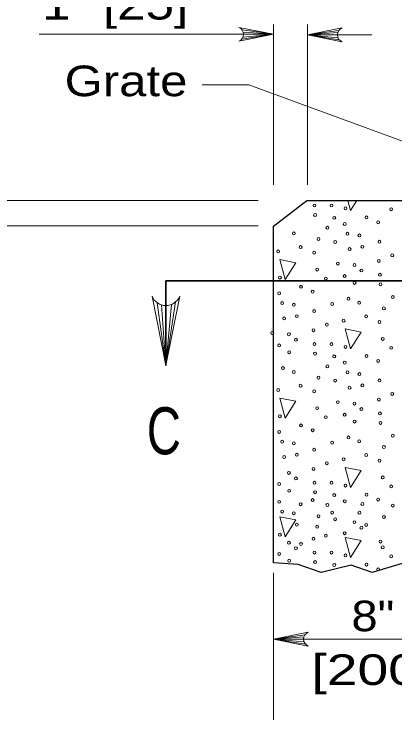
# Model space of a CAD drawing. Extents: x -410.5 to -376.5, y 1617.6 to 1661.6.
# Drawn here: x -396.1 to -394.159, y 1656.08 to 1659.678 of the extents above; entities that cross this region are included whole.
import ezdxf
from ezdxf.enums import TextEntityAlignment as Align

# ---------------------------------------------------------------- set-up
doc = ezdxf.new("R2010")
doc.units = 0
doc.header["$LTSCALE"] = 0.062
doc.layers.add('1', color=7, linetype='Continuous', lineweight=13)

msp = doc.modelspace()

# ---------------------------------------------------------------- linework, layer by layer
at = {"layer": '1'}
for p, q in [((-394.77725, 1658.80683), (-394.77725, 1659.62492)), ((-394.60417, 1658.80683), (-394.60417, 1659.62492)), ((-395.97325, 1659.575), (-394.77725, 1659.575)), ((-394.93942, 1659.55017), (-394.77725, 1659.575)), ((-394.9375, 1659.59742), (-394.77725, 1659.575)), ((-394.93325, 1659.56058), (-394.77725, 1659.575)), ((-394.93208, 1659.58633), (-394.77725, 1659.575)), ((-394.93042, 1659.575), (-394.77725, 1659.575)), ((-394.44492, 1659.59458), (-394.60517, 1659.57217)), ((-394.45033, 1659.5835), (-394.60517, 1659.57217)), ((-394.452, 1659.57217), (-394.60517, 1659.57217)), ((-394.44917, 1659.55775), (-394.60517, 1659.57217)), ((-394.44308, 1659.54733), (-394.60517, 1659.57217)), ((-394.60417, 1659.57217), (-394.27575, 1659.57217)), ((-400.65567, 1658.72817), (-394.85592, 1658.72817)), ((-400.62708, 1658.59883), (-394.85592, 1658.59883)), ((-394.74583, 1658.42658), (-394.71883, 1658.32417)), ((-394.66392, 1658.41067), (-394.74583, 1658.42658)), ((-394.71883, 1658.32417), (-394.66392, 1658.41067)), ((-395.37117, 1658.2065), (-395.32633, 1657.886)), ((-395.27683, 1658.21033), (-395.32633, 1657.886)), ((-395.29758, 1658.198), (-395.32633, 1657.886)), ((-395.349, 1658.19567), (-395.32633, 1657.886)), ((-395.32633, 1658.19233), (-395.32633, 1657.886)), ((-394.74583, 1657.71992), (-394.71883, 1657.61742)), ((-394.66392, 1657.70392), (-394.74583, 1657.71992)), ((-394.71883, 1657.61742), (-394.66392, 1657.70392)), ((-394.74583, 1657.11542), (-394.71883, 1657.01292)), ((-394.77725, 1656.07967), (-394.77725, 1656.82983)), ((-394.617, 1656.51367), (-394.77725, 1656.49125)), ((-394.6225, 1656.50258), (-394.77725, 1656.49125)), ((-394.62408, 1656.49125), (-394.77725, 1656.49125)), ((-394.62125, 1656.47683), (-394.77725, 1656.49125)), ((-394.61517, 1656.4665), (-394.77725, 1656.49125))]:
    msp.add_line(p, q, dxfattribs=at)
at = {"layer": '1', "lineweight": 25}
msp.add_line((-394.60742, 1658.72817), (-394.19133, 1658.72817), dxfattribs=at)
at = {"layer": '1', "lineweight": 35}
for q in [(-393.57875, 1658.31867), (-395.32633, 1657.886)]:
    msp.add_line((-395.32633, 1658.31867), q, dxfattribs=at)
at = {"layer": '1'}
for points in [[(-394.95425, 1659.53958), (-394.77725, 1659.575), (-394.95425, 1659.61033)], [(-394.42817, 1659.53675), (-394.60517, 1659.57217), (-394.42817, 1659.6075)], [(-393.31725, 1658.73575), (-394.90375, 1659.31708), (-395.14233, 1659.31708)], [(-394.39842, 1658.72808), (-394.38508, 1658.6775), (-394.35292, 1658.72808)], [(-395.25558, 1658.24), (-395.32633, 1657.886), (-395.39717, 1658.24)], [(-394.71883, 1657.01292), (-394.66392, 1657.09942), (-394.74583, 1657.11542)], [(-394.60025, 1656.45583), (-394.77725, 1656.49125), (-394.60025, 1656.52667)], [(-394.77725, 1656.49125), (-394.08308, 1656.49125), (-393.84033, 1656.49125)]]:
    msp.add_lwpolyline(points, dxfattribs=at)
at = {"layer": '1', "lineweight": 25}
for points in [[(-393.83325, 1656.87183), (-393.85467, 1656.87667), (-393.96075, 1656.85467), (-394.011, 1656.871), (-394.12183, 1656.87733), (-394.27542, 1656.83125), (-394.38142, 1656.86892), (-394.53508, 1656.83192), (-394.6515, 1656.87167), (-394.77725, 1656.87975), (-394.77725, 1658.5975), (-394.60742, 1658.72817), (-394.1165, 1658.72817)], [(-394.19133, 1658.72817), (-394.09692, 1658.72817), (-393.71933, 1658.72817)]]:
    msp.add_lwpolyline(points, dxfattribs=at)
at = {"layer": '1'}
for points in [[(-394.41208, 1658.07325), (-394.38508, 1657.97083), (-394.33008, 1658.05725)], [(-394.41208, 1657.3665), (-394.38508, 1657.26417), (-394.33008, 1657.35058)], [(-394.41208, 1657.01017), (-394.38508, 1656.90775), (-394.33008, 1656.99417)]]:
    msp.add_lwpolyline(points, close=True, dxfattribs=at)
for centre, radius, start, end in [((-394.96856, 1659.57501), 0.0382, 292.08605, 67.91218), ((-394.41389, 1659.57218), 0.0382, 112.08782, 247.91395), ((-395.32643, 1658.26863), 0.0764, 202.08782, 337.91395), ((-394.58598, 1656.49131), 0.0382, 112.08782, 247.91395)]:
    msp.add_arc(centre, radius, start, end, dxfattribs=at)
for centre, major_axis in [((-394.56882, 1658.70224), (0, -0.00756)), ((-394.48227, 1658.70224), (0, 0.00756)), ((-394.41112, 1658.68793), (0, -0.00756)), ((-394.17766, 1658.68316), (0, 0.00756)), ((-394.56615, 1658.6536), (0, -0.00756)), ((-394.46786, 1658.63929), (0, 0.00756)), ((-394.30387, 1658.64117), (0, -0.00756)), ((-394.50307, 1658.5887), (0, 0.00756)), ((-394.41474, 1658.60778), (0, 0.00756)), ((-394.24441, 1658.61638), (0, -0.00756)), ((-394.67456, 1658.55978), (0, -0.00756)), ((-394.40027, 1658.55819), (0, 0.00756)), ((-394.33992, 1658.54954), (0, -0.00756)), ((-394.5484, 1658.53116), (0, 0.00756)), ((-394.46341, 1658.5162), (0, 0.00756)), ((-394.23718, 1658.51709), (0, -0.00756)), ((-394.63946, 1658.49012), (0, 0.00756)), ((-394.38954, 1658.47993), (0, 0.00756)), ((-394.32462, 1658.49141), (0, -0.00756)), ((-394.75389, 1658.46815), (0, -0.00756)), ((-394.57093, 1658.46149), (0, 0.00756)), ((-394.17204, 1658.44813), (0, -0.00756)), ((-394.45017, 1658.40619), (0, 0.00756)), ((-394.24046, 1658.4195), (0, -0.00756)), ((-394.55469, 1658.37563), (0, 0.00756)), ((-394.36512, 1658.39883), (0, 0.00756)), ((-394.32968, 1658.37086), (0, -0.00756)), ((-394.74487, 1658.33458), (0, -0.00756)), ((-394.41501, 1658.34224), (0, 0.00756)), ((-394.23507, 1658.34889), (0, -0.00756)), ((-394.51141, 1658.32981), (0, 0.00756)), ((-394.36423, 1658.30755), (0, -0.00756)), ((-394.23239, 1658.30025), (0, -0.00756)), ((-394.63763, 1658.28782), (0, -0.00756)), ((-394.57816, 1658.26303), (0, -0.00756)), ((-394.74849, 1658.25443), (0, 0.00756)), ((-394.39577, 1658.22646), (0, -0.00756)), ((-394.16932, 1658.23535), (0, 0.00756)), ((-394.73403, 1658.20484), (0, 0.00756)), ((-394.67367, 1658.19619), (0, -0.00756)), ((-394.47871, 1658.19978), (0, -0.00756)), ((-394.34081, 1658.20643), (0, -0.00756)), ((-394.57093, 1658.16374), (0, -0.00756)), ((-394.21465, 1658.17781), (0, 0.00756)), ((-394.72329, 1658.12658), (0, 0.00756)), ((-394.65838, 1658.13806), (0, -0.00756)), ((-394.30571, 1658.13677), (0, 0.00756)), ((-394.5058, 1658.09478), (0, -0.00756)), ((-394.42013, 1658.1148), (0, -0.00756)), ((-394.23718, 1658.10814), (0, 0.00756)), ((-394.78392, 1658.05284), (0, 0.00756)), ((-394.69887, 1658.04548), (0, 0.00756)), ((-394.57421, 1658.06615), (0, -0.00756)), ((-394.66344, 1658.01751), (0, -0.00756)), ((-394.22094, 1658.02228), (0, 0.00756)), ((-394.74877, 1657.98889), (0, 0.00756)), ((-394.56882, 1657.99554), (0, -0.00756)), ((-394.48227, 1657.99554), (0, 0.00756)), ((-394.41112, 1657.98123), (0, -0.00756)), ((-394.17766, 1657.97646), (0, 0.00756)), ((-394.69798, 1657.9542), (0, -0.00756)), ((-394.56615, 1657.9469), (0, -0.00756)), ((-394.46786, 1657.93259), (0, 0.00756)), ((-394.30387, 1657.93447), (0, -0.00756)), ((-394.24441, 1657.90968), (0, -0.00756)), ((-394.72952, 1657.87311), (0, -0.00756)), ((-394.50307, 1657.882), (0, 0.00756)), ((-394.41474, 1657.90108), (0, 0.00756)), ((-394.67456, 1657.85308), (0, -0.00756)), ((-394.40027, 1657.85149), (0, 0.00756)), ((-394.33992, 1657.84284), (0, -0.00756)), ((-394.5484, 1657.82446), (0, 0.00756)), ((-394.46341, 1657.8095), (0, 0.00756)), ((-394.23718, 1657.81039), (0, -0.00756)), ((-394.75389, 1657.76145), (0, -0.00756)), ((-394.63946, 1657.78342), (0, 0.00756)), ((-394.38954, 1657.77323), (0, 0.00756)), ((-394.32462, 1657.78471), (0, -0.00756)), ((-394.57093, 1657.75479), (0, 0.00756)), ((-394.17204, 1657.74143), (0, -0.00756)), ((-394.45017, 1657.69949), (0, 0.00756)), ((-394.36512, 1657.69213), (0, 0.00756)), ((-394.24046, 1657.7128), (0, -0.00756)), ((-394.55469, 1657.66893), (0, 0.00756)), ((-394.32968, 1657.66416), (0, -0.00756)), ((-394.74487, 1657.62788), (0, -0.00756)), ((-394.51141, 1657.62311), (0, 0.00756)), ((-394.41501, 1657.63554), (0, 0.00756)), ((-394.23507, 1657.64219), (0, -0.00756)), ((-394.63763, 1657.58112), (0, -0.00756)), ((-394.36423, 1657.60085), (0, -0.00756)), ((-394.23239, 1657.59355), (0, -0.00756)), ((-394.74849, 1657.54773), (0, 0.00756)), ((-394.57816, 1657.55633), (0, -0.00756)), ((-394.39577, 1657.51976), (0, -0.00756)), ((-394.16932, 1657.52865), (0, 0.00756)), ((-394.73403, 1657.49814), (0, 0.00756)), ((-394.67367, 1657.48949), (0, -0.00756)), ((-394.47871, 1657.49308), (0, -0.00756)), ((-394.34081, 1657.49973), (0, -0.00756)), ((-394.21465, 1657.47111), (0, 0.00756)), ((-394.57093, 1657.45704), (0, -0.00756)), ((-394.72329, 1657.41988), (0, 0.00756)), ((-394.65838, 1657.43136), (0, -0.00756)), ((-394.42013, 1657.4081), (0, -0.00756)), ((-394.30571, 1657.43007), (0, 0.00756)), ((-394.23718, 1657.40144), (0, 0.00756)), ((-394.5058, 1657.38808), (0, -0.00756)), ((-394.69887, 1657.33878), (0, 0.00756)), ((-394.57421, 1657.35945), (0, -0.00756)), ((-394.66344, 1657.31081), (0, -0.00756)), ((-394.22094, 1657.31558), (0, 0.00756)), ((-394.74877, 1657.28219), (0, 0.00756)), ((-394.56882, 1657.28884), (0, -0.00756)), ((-394.48227, 1657.28884), (0, 0.00756)), ((-394.41112, 1657.27453), (0, -0.00756)), ((-394.17766, 1657.26976), (0, 0.00756)), ((-394.69798, 1657.2475), (0, -0.00756)), ((-394.56615, 1657.2402), (0, -0.00756)), ((-394.46786, 1657.22589), (0, 0.00756)), ((-394.30387, 1657.22777), (0, -0.00756)), ((-394.74849, 1657.19141), (0, 0.00756)), ((-394.57817, 1657.20001), (0, -0.00756)), ((-394.41474, 1657.19438), (0, 0.00756)), ((-394.24441, 1657.20298), (0, -0.00756)), ((-394.63946, 1657.17891), (0, 0.00756)), ((-394.50307, 1657.1753), (0, 0.00756)), ((-394.32462, 1657.18021), (0, -0.00756)), ((-394.16932, 1657.17233), (0, 0.00756)), ((-394.73403, 1657.14182), (0, 0.00756)), ((-394.67368, 1657.13317), (0, -0.00756)), ((-394.5484, 1657.11776), (0, 0.00756)), ((-394.47871, 1657.13676), (0, -0.00756)), ((-394.33992, 1657.13614), (0, -0.00756)), ((-394.21465, 1657.11479), (0, 0.00756)), ((-394.65838, 1657.07504), (0, -0.00756)), ((-394.46341, 1657.1028), (0, 0.00756)), ((-394.36512, 1657.08763), (0, 0.00756)), ((-394.30571, 1657.07374), (0, 0.00756)), ((-394.55469, 1657.06443), (0, 0.00756)), ((-394.32969, 1657.05966), (0, -0.00756)), ((-394.74488, 1657.02338), (0, -0.00756)), ((-394.57422, 1657.00313), (0, -0.00756)), ((-394.51141, 1657.01861), (0, 0.00756)), ((-394.41501, 1657.03103), (0, 0.00756)), ((-394.69887, 1656.98246), (0, 0.00756)), ((-394.63763, 1656.97662), (0, -0.00756)), ((-394.2324, 1656.98904), (0, -0.00756)), ((-394.66344, 1656.95449), (0, -0.00756)), ((-394.56882, 1656.93252), (0, -0.00756)), ((-394.48227, 1656.93252), (0, 0.00756)), ((-394.22094, 1656.95926), (0, 0.00756)), ((-394.74877, 1656.92587), (0, 0.00756)), ((-394.41112, 1656.91821), (0, -0.00756)), ((-394.17766, 1656.91344), (0, 0.00756)), ((-394.69798, 1656.89118), (0, -0.00756)), ((-394.56615, 1656.88388), (0, -0.00756)), ((-394.46786, 1656.86957), (0, 0.00756)), ((-394.30388, 1656.87145), (0, -0.00756)), ((-394.24441, 1656.84666), (0, -0.00756))]:
    msp.add_ellipse(centre, major_axis=major_axis, ratio=0.944543, dxfattribs=at)

# ---------------------------------------------------------------- texts
for s, width, p in [('1" [25]', 1.25, (-395.95758, 1659.65042)), ('Grate', 1.2, (-395.84283, 1659.2595))]:
    msp.add_text(s, height=0.156, dxfattribs=dict(at, width=width)).set_placement(p)
for s, height, width, p in [('C', 0.24, 0.75, (-395.33683, 1657.43358)), ('8"', 0.156, 1.15, (-394.27108, 1656.53175)), ('[200]', 0.156, 1.35, (-394.27108, 1656.25775))]:
    msp.add_text(s, height=height, dxfattribs=dict(at, width=width)).set_placement(p, align=Align.CENTER)

doc.saveas('drawing.dxf')
